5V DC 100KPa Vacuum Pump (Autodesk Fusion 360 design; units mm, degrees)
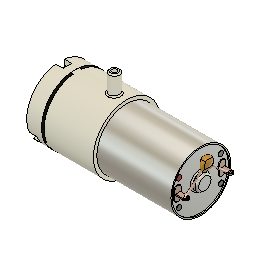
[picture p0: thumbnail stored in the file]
sketch "Sketch1" plane through (0, 0, 0) normal (1, 0, 0) x axis (0, 0, -1)
  circle C1 centre (0, 0) radius 13.5
  point P1 (0, 0)
  point P2 (0, 0)
  coincident P1 P2
  dimension "d1" diameter C1 = 27
extrude "Extrude1" new body sketch "Sketch1" along normal blind 3 bodies "Cap"
extrude "Extrude2" new body of existing geometry blind 3
extrude "Extrude3" new body of existing geometry blind 21 bodies "Body"
sketch "Sketch2" plane through (0, 0, 0) normal (-1, 0, 0) x axis (0, 0, 1)
  line L1 (1.75, 13.3861) -> (1.75, 11.25)
  line L2 (-1.75, 13.3861) -> (-1.75, 11.25)
  line L3 (-10.7177, -8.2086) -> (-8.8678, -7.1405)
  line L4 (-12.4677, -5.1775) -> (-10.6178, -4.1095)
  line L5 (12.4677, -5.1775) -> (10.6178, -4.1095)
  line L6 (10.7177, -8.2086) -> (8.8678, -7.1405)
  circle C1 centre (0, 0) radius 13.5
  circle C2 centre (0, 0) radius 1
  circle C3 centre (0, 0) radius 2.15
  arc A1 centre (0, 11.25) radius 1.75 clockwise from (1.75, 11.25) to (-1.75, 11.25)
  arc A2 centre (-9.7428, -5.625) radius 1.75 clockwise from (-10.6178, -4.1095) to (-8.8678, -7.1405)
  arc A3 centre (9.7428, -5.625) radius 1.75 clockwise from (8.8678, -7.1405) to (10.6178, -4.1095)
  point P7 (1.75, 13.3861)
  point P9 (-1.75, 13.3861)
  point P4 (0, 0)
  point P5 (0, 11.25)
  concentric C1 C2
  concentric C1 C3
  coincident C1 P7
  tangent L1 A1
  vertical L1
  coincident C1 P9
  tangent L2 A1
  parallel L1 L2
  dimension "d8" diameter C2 = 2
  dimension "d9" diameter C3 = 4.3
  dimension "d10" diameter A1 = 3.5
  dimension "d11" distance P4 P5 = 11.25
  dimension "d13" C-Pattern1-Angle = 360
extrude "Extrude4" cut sketch "Sketch2" profile of C1 A1 L1 L2 L3 L4 A2 L5 L6 A3 against normal blind 3
extrude "Extrude5" add sketch "Sketch2" profile of C2 C3 along normal blind 6
chamfer "Chamfer1" distance 0.5 rotateAngle 45
fillet "Fillet1" radius 0.5
combine "Combine1"
sketch "Sketch3" plane through (3, 0, 0) normal (-1, 0, 0) x axis (0, 0, 1)
  line L1 (10.7177, -8.2086) -> (8.8678, -7.1405)
  line L2 (10.6178, -4.1095) -> (12.4677, -5.1775)
  arc A1 centre (0, 0) radius 13.5 clockwise from (12.4677, -5.1775) to (10.7177, -8.2086)
  arc A2 centre (9.7428, -5.625) radius 1.75 clockwise from (8.8678, -7.1405) to (10.6178, -4.1095)
  arc A3 centre (0, 11.25) radius 1.75 clockwise from (1.75, 11.25) to (-1.75, 11.25)
  circle C1 centre (0, 11.25) radius 0.75
  circle C2 centre (-9.7428, -5.625) radius 0.75
  circle C3 centre (9.7428, -5.625) radius 0.75
  concentric A3 C1
  dimension "d21" diameter C1 = 1.5
  dimension "d23" C-Pattern1-Angle = 360
extrude "Extrude6" cut sketch "Sketch3" profile of C1 C2 C3 against normal blind 6
thread "Thread1"
thread "Thread2"
thread "Thread3"
sketch "Sketch4" plane through (6, 0, 0) normal (-1, 0, 0) x axis (0, 0, 1)
  curve K1 (-10.2668, -5.3118) -> (-10.2103, -6.182)
  curve K2 (-9.2752, -6.182) -> (-9.2187, -5.3118)
  curve K3 (-0.524, 11.5632) -> (-0.4676, 10.693)
  curve K4 (0.4676, 10.693) -> (0.524, 11.5632)
  curve K5 (9.2187, -5.3118) -> (9.2752, -6.182)
  curve K6 (10.2103, -6.182) -> (10.2668, -5.3118)
  line L1 (-1.75, 13.3861) -> (-1.75, 11.25)
  line L2 (1.75, 11.25) -> (1.75, 13.3861)
  line L3 (-10.6178, -4.1095) -> (-12.4677, -5.1775)
  line L4 (-10.7177, -8.2086) -> (-8.8678, -7.1405)
  line L5 (8.8678, -7.1405) -> (10.7177, -8.2086)
  line L6 (12.4677, -5.1775) -> (10.6178, -4.1095)
  line L7 (-10.6178, -4.1095) -> (-12.4677, -5.1775)
  line L8 (-10.7177, -8.2086) -> (-8.8678, -7.1405)
  line L9 (8.8678, -7.1405) -> (10.7177, -8.2086)
  line L10 (12.4677, -5.1775) -> (10.6178, -4.1095)
  arc A1 centre (-9.7428, -5.625) radius 0.6105 clockwise from (-10.2668, -5.3118) to (-9.2187, -5.3118)
  arc A2 centre (-9.7428, -5.625) radius 0.7272 clockwise from (-9.2752, -6.182) to (-10.2103, -6.182)
  arc A3 centre (0, 11.25) radius 0.6105 clockwise from (-0.524, 11.5632) to (0.524, 11.5632)
  arc A4 centre (0, 11.25) radius 0.7272 clockwise from (0.4676, 10.693) to (-0.4676, 10.693)
  arc A5 centre (9.7428, -5.625) radius 0.6105 clockwise from (9.2187, -5.3118) to (10.2668, -5.3118)
  arc A6 centre (9.7428, -5.625) radius 0.7272 clockwise from (10.2103, -6.182) to (9.2752, -6.182)
  circle C1 centre (0, 0) radius 13.5
  arc A7 centre (0, 11.25) radius 1.75 clockwise from (1.75, 11.25) to (-1.75, 11.25)
  arc A8 centre (0, 0) radius 13.5 clockwise from (1.75, 13.3861) to (12.4677, -5.1775)
  arc A9 centre (0, 0) radius 13.5 clockwise from (-12.4677, -5.1775) to (-1.75, 13.3861)
  arc A10 centre (-9.7428, -5.625) radius 1.75 clockwise from (-10.6178, -4.1095) to (-8.8678, -7.1405)
  arc A11 centre (0, 0) radius 13.5 clockwise from (10.7177, -8.2086) to (-10.7177, -8.2086)
  arc A12 centre (9.7428, -5.625) radius 1.75 clockwise from (8.8678, -7.1405) to (10.6178, -4.1095)
  arc A13 centre (0, 0) radius 13.5 clockwise from (-12.4677, -5.1775) to (-1.75, 13.3861)
  arc A14 centre (-9.7428, -5.625) radius 1.75 clockwise from (-10.6178, -4.1095) to (-8.8678, -7.1405)
  arc A15 centre (0, 0) radius 13.5 clockwise from (10.7177, -8.2086) to (-10.7177, -8.2086)
  arc A16 centre (9.7428, -5.625) radius 1.75 clockwise from (8.8678, -7.1405) to (10.6178, -4.1095)
  dimension "d27" C-Pattern1-Angle = 360
  dimension "d29" C-Pattern2-Angle = 360
extrude "Extrude7" cut sketch "Sketch4" profile of C1 A7 L1 L2 A8 A9 L3 A10 L4 A11 L5 A12 L6 A13 L7 A14 L8 A15 L9 A16 L10 against normal blind 1
extrude "Extrude8" new body sketch "Sketch4" profile of C1 A7 L1 L2 A8 A9 L3 A10 L4 A11 L5 A12 L6 A13 L7 A14 L8 A15 L9 A16 L10 against normal blind 1 bodies "Gasket"
base_feature "Base Feature1"
position "Position1"
component_from_bodies "Body->Comp1"
component_from_bodies "Body->Comp2"
component_from_bodies "Body->Comp3"
as_built_joint "As-built1"
as_built_joint "As-built2"
joint "Assemble1" alignAngle 0 alignOffsetX 0 alignOffsetY 0 alignOffsetZ 0
copy_paste "CopyPaste1"
joint "Assemble2" alignAngle 0 alignOffsetX 0 alignOffsetY 0 alignOffsetZ 0
copy_paste "CopyPaste2"
joint "Assemble3" alignAngle 180 alignOffsetX 0 alignOffsetY 0 alignOffsetZ 0
work_plane "WorkPlane1" RotateAngle 0
sketch "Sketch5" plane through (24.8535, 13.5, 0) normal (0, 1, 0) x axis (0, 0, -1)
  line L1 (1.75, 24.8535) -> (-1.75, 24.8535)
  line L2 (0, 9.9659) -> (0, 0)
  circle C1 centre (0, 2.8535) radius 2.1
  circle C2 centre (0, 2.8535) radius 1
  point P1 (0, 0)
  point P6 (0, 0)
  point P4 (0, 2.8535)
  concentric C1 C2
  coincident P1 P6
  vertical L2
  dimension "d71" diameter C1 = 4.2
  dimension "d72" distance L1 P4 = 22
  dimension "d73" diameter C2 = 2
extrude "Extrude1" add sketch "Sketch5" profile of C1 C2 along normal blind 7.7 and against normal blind 1
chamfer "Chamfer1" distance 0.5 rotateAngle 45
fillet "Fillet1" radius 0.5
sketch "Sketch6" plane through (27, 0, 0) normal (1, 0, 0) x axis (0, 0, -1)
  circle C1 centre (0, 0) radius 13.5
  circle C2 centre (0, 0) radius 12.1
  concentric C1 C2
  dimension "d81" diameter C2 = 24.2
extrude "Extrude9" new body sketch "Sketch6" profile of C2 along normal blind 30 bodies "Housing"
component_from_bodies "Body->Comp4"
shell "Shell1" innerThickness 0.5
work_plane "WorkPlane1" AlongDistance -0.5
sketch "Sketch1" plane through (56.5, 0, 0) normal (1, 0, 0) x axis (0, 0, -1)
  line L1 (7.5, -1.5) -> (7.5, 1.5)
  line L2 (10.5, 1.5) -> (10.5, -1.5)
  line L3 (9, -1.5) -> (9, 1.5)
  line L4 (8, -0.25) -> (10, -0.25)
  line L5 (8, 0.25) -> (8, -0.25)
  line L6 (10, 0.25) -> (8, 0.25)
  line L7 (10, -0.25) -> (10, 0.25)
  line L8 (8, 0.25) -> (10, -0.25)
  line L9 (10, 0.25) -> (8, -0.25)
  line L10 (-10, -0.25) -> (-8, -0.25)
  line L11 (-10, 0.25) -> (-10, -0.25)
  line L12 (-8, -0.25) -> (-8, 0.25)
  line L13 (-8, 0.25) -> (-10, 0.25)
  line L14 (-7.5, 1.5) -> (-7.5, -1.5)
  line L15 (-10.5, -1.5) -> (-10.5, 1.5)
  line L16 (1.7577, 0) -> (-1.4537, 0)
  line L17 (0, -1.7961) -> (0, 1.7746)
  circle C1 centre (0, 0) radius 11.6
  circle C2 centre (0, 0) radius 3.25
  arc A1 centre (9, -1.5) radius 1.5 clockwise from (10.5, -1.5) to (7.5, -1.5)
  arc A2 centre (9, 1.5) radius 1.5 clockwise from (7.5, 1.5) to (10.5, 1.5)
  arc A3 centre (-9, 1.5) radius 1.5 clockwise from (-10.5, 1.5) to (-7.5, 1.5)
  arc A4 centre (-9, -1.5) radius 1.5 clockwise from (-7.5, -1.5) to (-10.5, -1.5)
  circle C3 centre (0, 0) radius 10
  circle C4 centre (8.4763, -5.2108) radius 1
  circle C5 centre (8.4763, 5.2108) radius 1
  circle C6 centre (-8.4763, 5.2108) radius 1
  circle C7 centre (-8.4763, -5.2108) radius 1
  point P10 (9, 0)
  point P15 (9, 0)
  point P9 (9, -1.5)
  point P3 (0, 0)
  point P13 (8, 0.25)
  point P14 (10, 0.25)
  point P12 (8, -0.25)
  concentric C1 C2
  tangent L1 A1
  tangent A1 L2
  parallel L1 L2
  tangent L2 A2
  tangent L1 A2
  vertical L3
  midpoint L3 P10
  horizontal L4
  perpendicular L4 L5
  parallel L4 L6
  parallel L5 L7
  coincident L8 P15
  coincident L9 P15
  coincident P10 P15
  concentric C1 C3
  horizontal L16
  perpendicular L16 L17
  symmetric C4 L16 C5
  symmetric C4 L17 C7
  symmetric L17 C5 C6
  dimension "d86" diameter C2 = 6.5
  dimension "d87" distance P9 P10 = 1.5
  dimension "d88" diameter A1 = 3
  dimension "d89" distance P3 P10 = 9
  dimension "d90" distance P13 P14 = 2
  dimension "d91" distance P12 P13 = 0.5
  dimension "d94" diameter C3 = 20
  dimension "d95" diameter C4 = 2
  dimension "d93" C-Pattern1-Angle = 360
extrude "Extrude1" add sketch "Sketch1" profile of C1 C2 L1 A1 L2 A2 L4 L5 L6 L7 L10 L11 L12 L13 L14 A3 A4 L15 C4 C5 C6 C7 to an object
extrude "Extrude2" add sketch "Sketch1" profile of C2 along normal blind 2.15
fillet "Fillet1" radius 0.75
extrude "Extrude3" new body sketch "Sketch1" profile of L4 L5 L6 L7 L10 L11 L12 L13 along normal blind 4.5
fillet "Fillet2" radius 0.95
extrude "Extrude4" new body sketch "Sketch1" profile of C4 C5 C6 C7 along normal blind 0.25
extrude "Extrude5" new body sketch "Sketch1" profile of L1 A1 L2 A2 L4 L5 L6 L7 L10 L11 L12 L13 L14 A3 A4 L15 along normal blind 0.25 bodies "Pos Lead"
combine "Combine1" bodies "Neg Lead"
sketch "Sketch2" plane through (0, -0.25, 0) normal (0, -1, 0) x axis (1, 0, 0)
  line L1 (56.75, -10) -> (56.75, -8)
  line L2 (60.05, -10) -> (56.75, -10)
  line L3 (61, -8.95) -> (61, -9.05)
  line L4 (56.75, -8) -> (60.05, -8)
  line L5 (61, -9.05) -> (61, -8.95)
  line L6 (61, 8.95) -> (61, 9.05)
  line L7 (58.65, -2.5) -> (58.65, 2.5)
  line L8 (62.07, 0) -> (58.65, 0)
  arc A1 centre (60.05, -9.05) radius 0.95 clockwise from (61, -9.05) to (60.05, -10)
  arc A2 centre (60.05, -8.95) radius 0.95 clockwise from (60.05, -8) to (61, -8.95)
  circle C1 centre (60, 9) radius 0.625
  circle C2 centre (60, -9) radius 0.625
  point P17 (58.65, 0)
  point P14 (60, 9)
  midpoint L7 P17
  perpendicular L7 L8
  symmetric C1 L8 C2
  dimension "d108" diameter C1 = 1.25
  dimension "d109" distance L6 P14 = 1
extrude "Extrude6" cut sketch "Sketch2" profile of C1 C2 against normal blind 1
fillet "Fillet3" radius 0.2
work_plane "WorkPlane2" AlongDistance 2.875
sketch "Sketch7" plane through (59.375, 0, 0) normal (1, 0, 0) x axis (0, 0, -1)
  curve K1 (-0.013, 5.5568) -> (-2.25, 7.8177)
  curve K2 (-2.3445, 6.9571) -> (-2.1554, 8.6783)
  curve K3 (-2.4645, 5.4301) -> (-2.6512, 5.658)
  line L1 (0, 6.7321) -> (0, 7.8067)
  curve K4 (0.013, 5.5568) -> (2.25, 7.8177)
  curve K5 (0.9321, 5.642) -> (-0.9581, 5.4716)
  curve K6 (2.3445, 6.9571) -> (2.1554, 8.6783)
  curve K7 (2.4645, 5.4301) -> (2.6512, 5.658)
  curve K8 (-0.9321, 5.642) -> (0.9581, 5.4716)
  curve K9 (-9.8454, -0.6068) -> (-2.1262, 6.0822)
  curve K10 (-10.8615, -1.1572) -> (-8.8294, -0.0565)
  curve K11 (9.8454, -0.6068) -> (2.1262, 6.0822)
  curve K12 (-2.7769, 5.334) -> (-1.4756, 6.8303)
  curve K13 (2.7769, 5.334) -> (1.4756, 6.8303)
  curve K14 (10.8615, -1.1572) -> (8.8294, -0.0565)
  arc A1 centre (0, 7.8067) radius 2.25 clockwise from (0.013, 5.5568) to (-0.013, 5.5568)
  arc A2 centre (0, 7.8067) radius 2.25 clockwise from (-2.25, 7.8177) to (2.25, 7.8177)
  point P3 (-2.25, 7.8177)
  point P4 (-2.5578, 5.544)
  point P2 (0, 7.8067)
  point P10 (0, 7.8067)
  point P5 (-0.013, 5.5568)
  point P12 (2.25, 7.8177)
  point P13 (2.5578, 5.544)
  point P14 (0.013, 5.5568)
  point P6 (-2.1554, 8.6783)
  point P17 (2.1554, 8.6783)
  point P7 (-2.3445, 6.9571)
  point P18 (2.3445, 6.9571)
  point P8 (-2.6512, 5.658)
  point P19 (2.6512, 5.658)
  point P9 (-2.4645, 5.4301)
  point P20 (2.4645, 5.4301)
  point P15 (-0.9581, 5.4716)
  point P21 (0.9581, 5.4716)
  point P16 (0.9321, 5.642)
  point P22 (-0.9321, 5.642)
  point P23 (0.013, 5.5568)
  point P26 (-9.8454, -0.6068)
  point P25 (-2.1262, 6.0822)
  point P29 (2.1262, 6.0822)
  point P30 (9.8454, -0.6068)
  point P27 (-8.8294, -0.0565)
  point P35 (8.8294, -0.0565)
  point P28 (-10.8615, -1.1572)
  point P36 (10.8615, -1.1572)
  point P31 (-1.4756, 6.8303)
  point P33 (1.4756, 6.8303)
  point P32 (-2.7769, 5.334)
  point P34 (2.7769, 5.334)
  midpoint P3 K2
  midpoint P4 K3
  coincident P2 P10
  vertical L1
  midpoint P5 K5
  symmetric P3 L1 P12
  symmetric P4 L1 P13
  symmetric P5 L1 P14
  symmetric P6 L1 P17
  symmetric P7 L1 P18
  symmetric P8 L1 P19
  symmetric P9 L1 P20
  symmetric L1 P15 P21
  symmetric L1 P16 P22
  coincident K4 P23
  concentric A1 A2
  midpoint P26 K10
  midpoint P25 K12
  symmetric L1 P25 P29
  symmetric L1 P26 P30
  symmetric L1 P27 P35
  symmetric L1 P28 P36
  symmetric L1 P31 P33
  symmetric L1 P32 P34
  dimension "d114" diameter A1 = 4.5
form "Form3"
form "Form4"
work_plane "WorkPlane4" PathDistance 0.2826
sketch "Sketch10" plane through (59.375, 3.9433, 4.0874) normal (0, -0.7175, 0.6966) x axis (1, 0, 0)
  circle C1 centre (0, 0) radius 0.375
  point P1 (0, 0)
  point P2 (0, 0)
  coincident P1 P2
  dimension "d120" diameter C1 = 0.75
work_plane "WorkPlane5" PathDistance 0.3275
sketch "Sketch11" plane through (59.375, 3.614, -4.4105) normal (0, -0.7099, -0.7043) x axis (1, 0, 0)
  circle C1 centre (0, 0) radius 0.375
  point P1 (0, 0)
  point P2 (0, 0)
  coincident P1 P2
  dimension "d122" diameter C1 = 0.75
sweep "Sweep1" sketch "Sketch10" TwistAngle 0 TaperAngle 0
sweep "Sweep2" sketch "Sketch11" TwistAngle 0 TaperAngle 0
copy_paste_bodies "CutPasteBodies"
fillet "Fillet4" radius 0.5
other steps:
base_feature "Base Feature1" bodies "Cap"
base_feature "Base Feature1" bodies "Body"
base_feature "Base Feature1" bodies "Gasket"
base_feature "Base Feature1"
base_feature "Base Feature1" bodies "Housing"
create_component "CreateComponent1"
create_component "CreateComponent2"
remove_body "RemoveBody1"
create_component "CreateComponent3"
remove_body "RemoveBody2"
create_component "CreateComponent4"
remove_body "RemoveBody3"
joint_origin "JointOrigin1" OffsetX 0 OffsetY 0 OffsetZ 0 AngleZ 0
joint_origin "JointOrigin1" OffsetX 0 OffsetY 0 OffsetZ 0 AngleZ 0
joint_origin "JointOrigin2" OffsetX 0 OffsetY 0 OffsetZ 0 AngleZ 0
joint_origin "JointOrigin2" OffsetX 0 OffsetY 0 OffsetZ 0 AngleZ 0
joint_origin "JointOrigin3" OffsetX 0 OffsetY 0 OffsetZ 0 AngleZ 0
joint_origin "JointOrigin3" OffsetX 0 OffsetY 0 OffsetZ 0 AngleZ 0
create_component "CreateComponent5"
remove_body "RemoveBody4"
create_component "CreateComponent6"
remove_body "RemoveBody5"
remove_body "RemoveBody6"
remove_body "RemoveBody7"
named bodies: "Cap", "Body", "Gasket", "Housing", "Pos Lead", "Neg Lead"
